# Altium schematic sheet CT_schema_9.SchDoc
size 274 x 160 mm
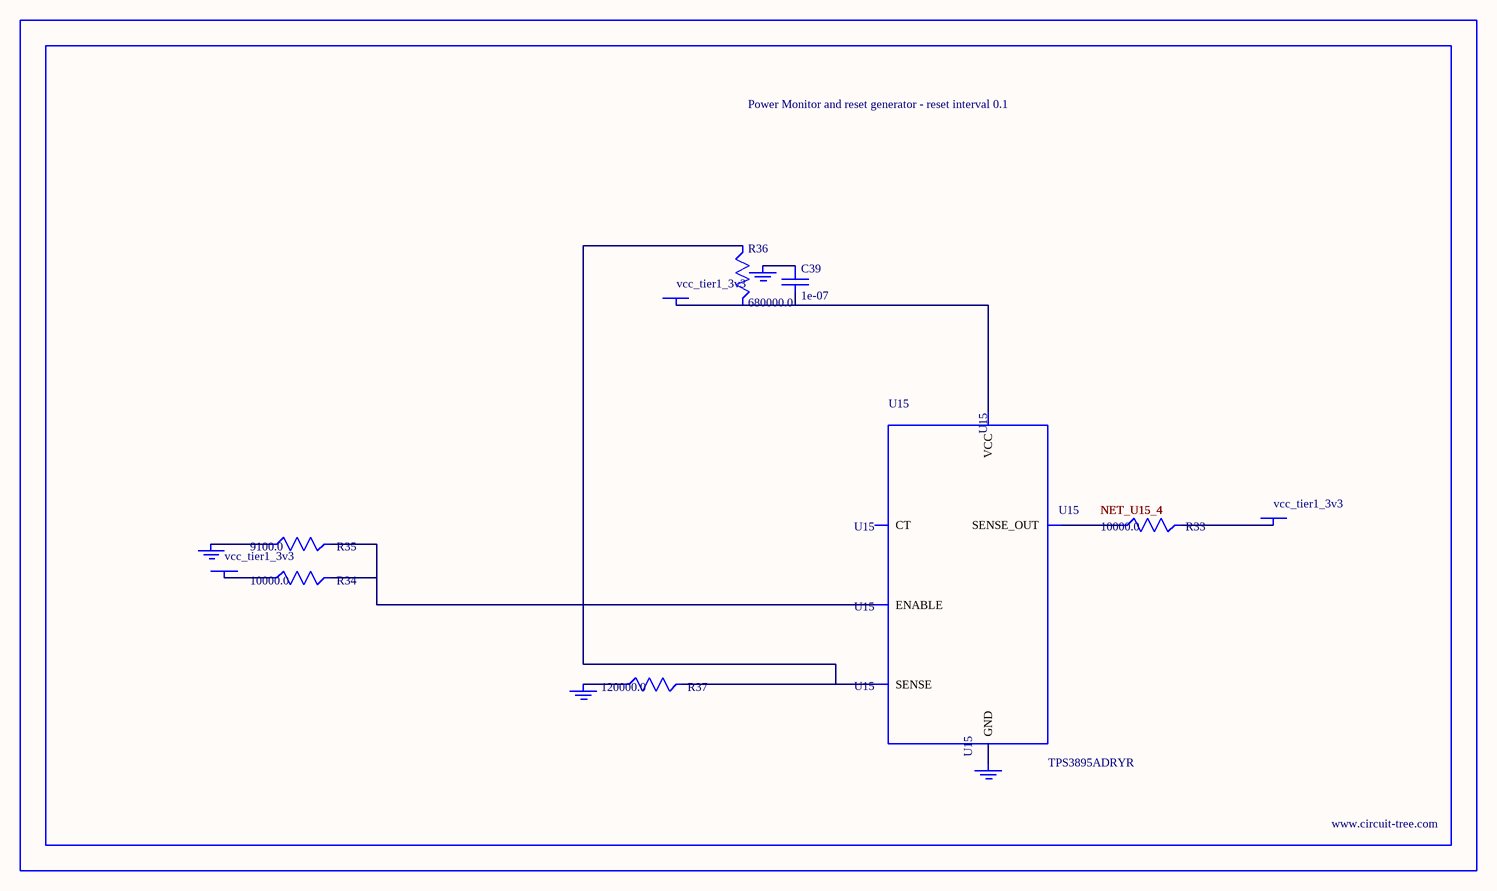
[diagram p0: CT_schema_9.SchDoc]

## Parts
BORDER8  (no value)
C39  1e-07  [C0402]
GND_INSTANCE_8_0  (no value)
GND_INSTANCE_8_1  (no value)
GND_INSTANCE_8_2  (no value)
GND_INSTANCE_8_3  (no value)
POWER_INSTANCE_8_0  vcc_tier1_3v3
POWER_INSTANCE_8_1  vcc_tier1_3v3
POWER_INSTANCE_8_2  vcc_tier1_3v3
R33  10000.0  [R0603]
R34  10000.0  [R0603]
R35  9100.0  [R0603]
R36  680000.0  [R0603]
R37  120000.0  [R0603]
U15  TPS3895ADRYR  [SON-6]

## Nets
NetC39_1: C39.1 GND_INSTANCE_8_2.0(GND)
NetC39_2: C39.2 POWER_INSTANCE_8_2.0(PWR) R36.2 U15.6(VCC)
NetGND_INSTANCE_8_0_0: GND_INSTANCE_8_0.0(GND) R35.1
NetGND_INSTANCE_8_1_0: GND_INSTANCE_8_1.0(GND) R37.1
NetGND_INSTANCE_8_3_0: GND_INSTANCE_8_3.0(GND) U15.2(GND)
NetPOWER_INSTANCE_8_0_0: POWER_INSTANCE_8_0.0(PWR) R34.1
NetPOWER_INSTANCE_8_1_0: POWER_INSTANCE_8_1.0(PWR) R33.2
NetR33_1: R33.1 U15.4(SENSE_OUT)
NetR34_2: R34.2 R35.2 U15.1(ENABLE)
NetR36_1: R36.1 R37.2 U15.3(SENSE)

Not connected (* = marked no-connect by the designer): U15 5(CT)

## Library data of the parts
BORDER8 = BORDER_PAGE8
C39 = C0402C104K3RACTU
GND_INSTANCE_8_0-GND_INSTANCE_8_3 = GND
POWER_INSTANCE_8_0-POWER_INSTANCE_8_2 = PWR
R33 R34 = RC0603JR-0710KL
R35 = RC0603JR-079K1L
R36 = RC0603JR-07680KL
R37 = RC0603JR-07120KL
